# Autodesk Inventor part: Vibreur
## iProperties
Created: 2010-07
Part Number: Vibreur
Document SubType Name: Modeling
Designer: eric
Density: 1 g/cm^3
Mass: 0.180838 g
Surface Area: 5.34856 cm^2
Volume: 0.180838 cm^3
Author: eric
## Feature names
1. Revolution1
2. Hole1
